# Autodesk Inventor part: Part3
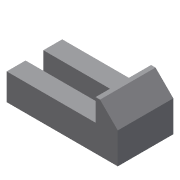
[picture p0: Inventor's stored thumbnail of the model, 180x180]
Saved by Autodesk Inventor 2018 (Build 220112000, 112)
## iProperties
Shininess: 77.0
Length Units: 11269
Angle Units: 11279
Time Units: 11290
Mass Units: 11283
Length Display Precision: 3
Angle Display Precision: 2
Created: 2002-01
Part Number: Part3
Document SubType Name: Modeling
Designer: ***
Density: 1 g/cm^3
Material: Generic
Appearance: Default
Density: 0.0
Volumn: 0.0
Area: 0.0
PropertySet Name: Model Information
Control State: 0
Master: False
Checked Out: False
Author: ***
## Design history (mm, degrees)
sketch "Sketch2"
  geometry: L1 (23.289, -5.477)-(-16.711, -5.477); L2 (-16.711, -5.477)-(-16.711, 4.523); L3 (-16.711, 4.523)-(-18.711, 4.523); L4 (-18.711, 4.523)-(-26.711, -3.477); L5 (-26.711, -3.477)-(-26.711, -17.477); L6 (-26.711, -17.477)-(23.289, -17.477); L7 (23.289, -17.477)-(23.289, -5.477)
  constraints: 14 end point, 4 parallel, 1 horizontal, 1 perpendicular
  dimensions: "d0" = 50 distance of L5.end L6.end; "d1" = 12 distance of L6.end L1.start; "d2" = 22 distance between parallel lines of L3 L6; "d3" = 135 deg angle of L5 L4; "d4" = 2 distance of L2.end L3.end; "d5" = 40 distance of L1.start L1.end
extrude "Extrusion1" new body sketch "Sketch2" stored distance "d6" = 25; taper "d7" = 0 deg
sketch "Sketch3"
  geometry: L1 (-4, -8.5)-(36, -8.5); L2 (36, -8.5)-(36, -16.5); L3 (36, -16.5)-(-4, -16.5); L4 (-4, -16.5)-(-4, -8.5); L5 (40, -25)-(40, 0) reference; L6 (40, 0)-(0, 0) reference
  constraints: 8 end point, 2 parallel, 1 horizontal, 1 perpendicular
  dimensions: "d8" = 8 distance of L1.end L2.end; "d9" = 40 distance of L1.start L1.end; "d10" = 4 distance between parallel lines of L5 L2; "d11" = 8.5 distance between parallel lines of L6 L1
extrude "Extrusion2" cut sketch "Sketch3" extent not by distance; stored distance "d12" = 25; taper "d13" = 0 deg
body "Solid1"
